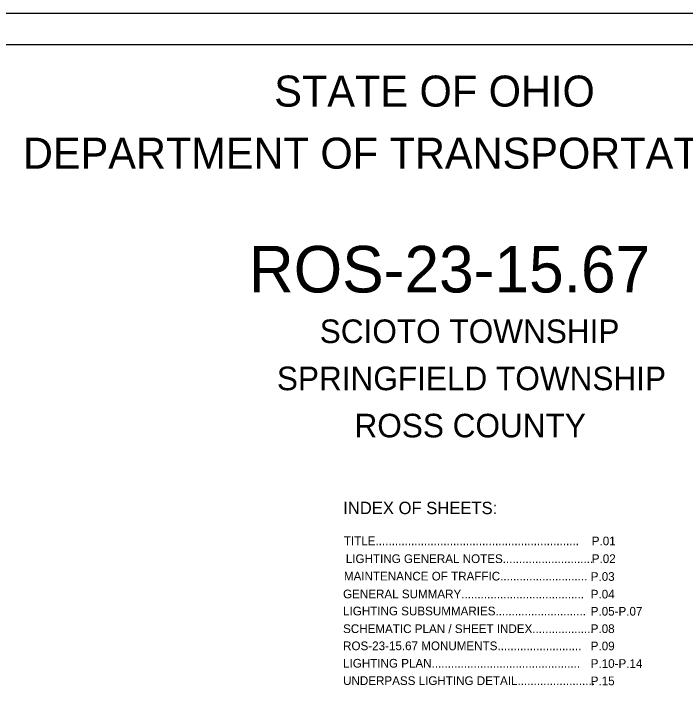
# Model space of a CAD drawing. Extents: x 0 to 34, y 0 to 22.
# Drawn here: x 9.77 to 20.59, y 11.11 to 22 of the extents above; entities that cross this region are included whole.
import ezdxf

# ---------------------------------------------------------------- set-up
doc = ezdxf.new("R2010")
doc.units = 0
for name, color, linetype in [('SH_Border', 7, 'Continuous'), ('SH_Cut_Line', 7, 'Continuous'), ('SH_Data', 7, 'Continuous')]:
    doc.layers.add(name, color=color, linetype=linetype)

msp = doc.modelspace()

# ---------------------------------------------------------------- linework, layer by layer
at = {"layer": 'SH_Border'}
msp.add_lwpolyline([(1.5, 21.5), (33.5, 21.5), (33.5, 0.5), (1.5, 0.5)], close=True, dxfattribs=at)
at = {"layer": 'SH_Cut_Line'}
msp.add_lwpolyline([(0, 0), (34, 0), (34, 22), (0, 22)], close=True, dxfattribs=at)

# ---------------------------------------------------------------- texts
at = {"layer": 'SH_Data'}
for s, height, p in [('STATE OF OHIO', 0.5, (13.968, 20.5)), ('DEPARTMENT OF TRANSPORTATION', 0.5, (9.92, 19.5)), ('ROS-23-15.67', 0.75, (13.558, 17.505)), ('SCIOTO TOWNSHIP', 0.38, (14.701, 16.69)), ('SPRINGFIELD TOWNSHIP', 0.38, (14.011, 15.93)), ('ROSS COUNTY', 0.38, (15.261, 15.17)), ('INDEX OF SHEETS:', 0.2, (15.079, 13.933)), ('TITLE...............................................................', 0.14, (15.09, 13.433)), ('P.01', 0.14, (19.083, 13.431)), ('LIGHTING GENERAL NOTES............................', 0.14, (15.121, 13.145)), ('P.02', 0.14, (19.083, 13.146)), ('MAINTENANCE OF TRAFFIC...........................', 0.14, (15.09, 12.864)), ('P.03', 0.14, (19.066, 12.858)), ('GENERAL SUMMARY......................................', 0.14, (15.077, 12.577)), ('P.04', 0.14, (19.066, 12.574)), ('LIGHTING SUBSUMMARIES............................', 0.14, (15.077, 12.302)), ('P.05-P.07', 0.14, (19.066, 12.298)), ('SCHEMATIC PLAN / SHEET INDEX...................', 0.14, (15.077, 12.017)), ('P.08', 0.14, (19.066, 12.017)), ('ROS-23-15.67 MONUMENTS..........................', 0.14, (15.077, 11.741)), ('P.09', 0.14, (19.066, 11.739)), ('LIGHTING PLAN..............................................', 0.14, (15.077, 11.46)), ('P.10-P.14', 0.14, (19.066, 11.456)), ('UNDERPASS LIGHTING DETAIL........................', 0.14, (15.077, 11.18)), ('P.15', 0.14, (19.066, 11.176))]:
    msp.add_text(s, height=height, dxfattribs=at).set_placement(p)

doc.saveas('drawing.dxf')
